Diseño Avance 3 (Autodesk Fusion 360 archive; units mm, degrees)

design "Diseño para imprimir" references "ESP32S3 Super Mini", "TOF", "przelacznik", "Tornillo grueso en forma de rosca sin ranura de arandela hexagonal 30° 5x8 Acero al carbono Negro"
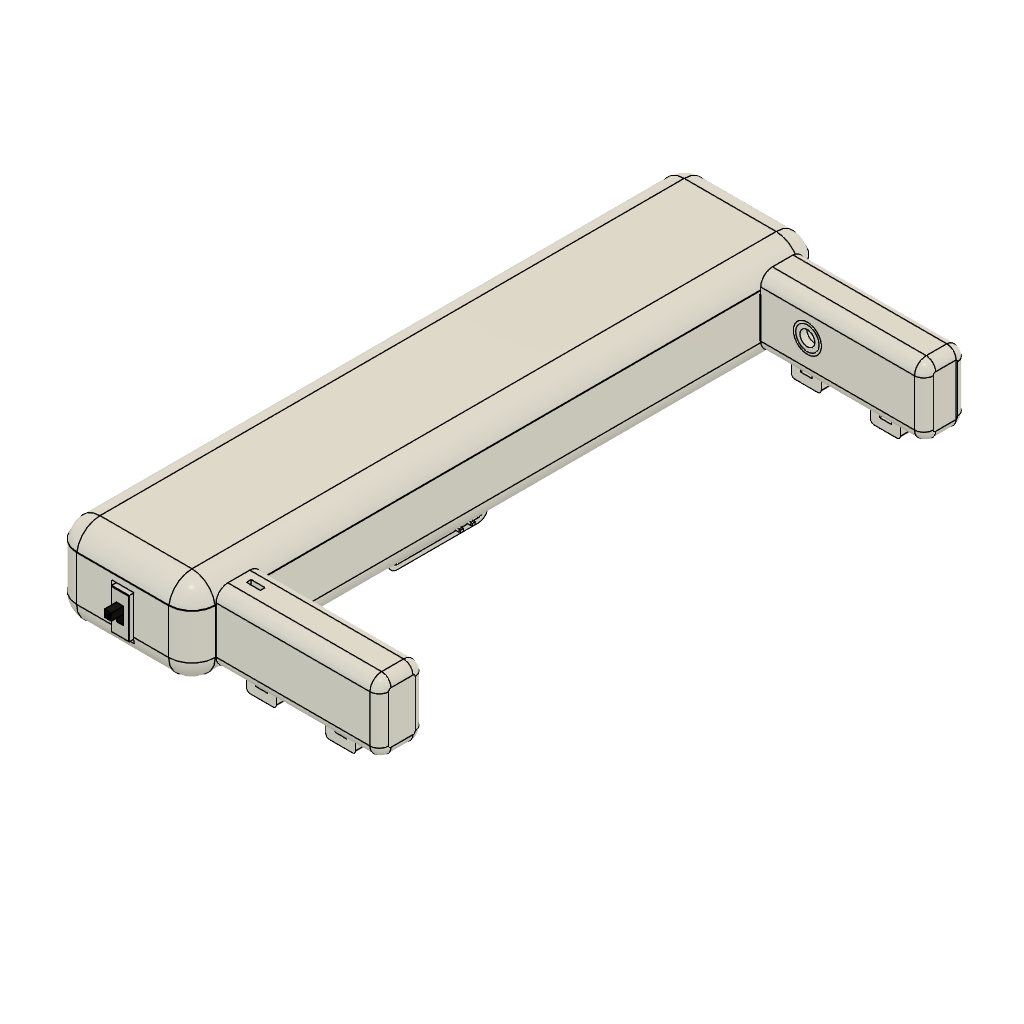
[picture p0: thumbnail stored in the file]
part number: 2026-10-26-12-19-18-322
parameter "d70" = 1.5
parameter "d71" = 2
parameter "d72" = 0.75 (= "0.5 * d70")
parameter "d73" = 0.5
parameter "d74" = 0.1
component_insert "Inserción de componente2"
sketch "Boceto2" plane through (0, 0, 0) normal (0, 1, 0) x axis (1, 0, 0)
  line L1 (11.8049, 39.8827) -> (-7.939, 39.8827)
  line L2 (16.8049, -90.4755) -> (16.8049, 34.8827)
  line L3 (-7.939, -95.4755) -> (11.8049, -95.4755)
  line L4 (-12.939, 34.8827) -> (-12.939, -90.4755)
  arc A1 centre (11.8049, 34.8827) radius 5 clockwise from (11.8049, 39.8827) to (16.8049, 34.8827)
  arc A2 centre (-7.939, 34.8827) radius 5 clockwise from (-12.939, 34.8827) to (-7.939, 39.8827)
  arc A3 centre (11.8049, -90.4755) radius 5 clockwise from (16.8049, -90.4755) to (11.8049, -95.4755)
  arc A4 centre (-7.939, -90.4755) radius 5 clockwise from (-7.939, -95.4755) to (-12.939, -90.4755)
  horizontal L1
  vertical L2
  horizontal L3
  vertical L4
  tangent L1 A1
  tangent L2 A1
  tangent L1 A2
  tangent L4 A2
  equal A1 A2
  tangent L2 A3
  tangent L3 A3
  equal A1 A3
  tangent L3 A4
  tangent L4 A4
  equal A1 A4
  dimension "d1" radius A1 = 5
extrude "Extruir1" new body sketch "Boceto2" along normal blind 20 bodies "Tapa modelo principal"
fillet "Empalme1" radius 5
shell "Vaciado1" innerThickness 1
sketch "Boceto3" plane through (-12.939, 0, 0) normal (-1, 0, 0) x axis (0, 0, 1)
  line L1 (-34.8827, 15) -> (90.4755, 15)
  line L2 (-34.8827, 5) -> (-34.8827, 15)
  line L3 (90.4755, 5) -> (-34.8827, 5)
  line L4 (90.4755, 15) -> (90.4755, 5)
  line L5 (100, 15) -> (-41.9189, 15.051)
split "Dividir1" bodies "Cuerpo modelo principal"
move "Desplazar1"
move "Desplazar2"
move "Desplazar3"
sketch "Boceto4" plane through (0, 0, -40.8827) normal (0, 0, -1) x axis (-1, 0, 0)
  line L1 (-9.8049, 35) -> (9.939, 35)
  line L2 (-9.8049, 25) -> (-9.8049, 35)
  line L3 (9.939, 25) -> (-9.8049, 25)
  line L4 (9.939, 35) -> (9.939, 25)
  line L5 (4.6443, 30.227) -> (-4.4043, 30.227)
  line L6 (5.5543, 27.1633) -> (5.5543, 29.317)
  line L7 (-4.4043, 26.2533) -> (4.6443, 26.2533)
  line L8 (-5.3143, 29.317) -> (-5.3143, 27.1633)
  arc A1 centre (-4.4043, 29.317) radius 0.91 clockwise from (-5.3143, 29.317) to (-4.4043, 30.227)
  arc A2 centre (4.6443, 29.317) radius 0.91 clockwise from (4.6443, 30.227) to (5.5543, 29.317)
  arc A3 centre (-4.4043, 27.1633) radius 0.91 clockwise from (-4.4043, 26.2533) to (-5.3143, 27.1633)
  arc A4 centre (4.6443, 27.1633) radius 0.91 clockwise from (5.5543, 27.1633) to (4.6443, 26.2533)
  horizontal L5
  vertical L6
  horizontal L7
  vertical L8
  tangent L5 A1
  tangent L8 A1
  tangent L5 A2
  tangent L6 A2
  equal A1 A2
  tangent L7 A3
  tangent L8 A3
  equal A1 A3
  tangent L6 A4
  tangent L7 A4
  equal A1 A4
  dimension "d7" radius A1 = 0.91
extrude "Extruir2" cut sketch "Boceto4" profile of L5 L6 L7 L8 A1 A2 A3 A4 distance 5
sketch "Boceto6" plane through (0, 0, 0) normal (0, 1, 0) x axis (1, 0, 0)
  line L1 (-6.6748, -37.6034) -> (5.6853, -37.6034)
  line L2 (-8.6748, -18.2148) -> (-8.6748, -35.6034)
  line L3 (5.6853, -16.2148) -> (-6.6748, -16.2148)
  line L4 (7.6853, -35.6034) -> (7.6853, -18.2148)
  arc A1 centre (5.6853, -35.6034) radius 2 clockwise from (7.6853, -35.6034) to (5.6853, -37.6034)
  arc A2 centre (5.6853, -18.2148) radius 2 clockwise from (5.6853, -16.2148) to (7.6853, -18.2148)
  arc A3 centre (-6.6748, -18.2148) radius 2 clockwise from (-8.6748, -18.2148) to (-6.6748, -16.2148)
  arc A4 centre (-6.6748, -35.6034) radius 2 clockwise from (-6.6748, -37.6034) to (-8.6748, -35.6034)
  horizontal L1
  vertical L2
  horizontal L3
  vertical L4
  tangent L1 A1
  tangent L4 A1
  tangent L3 A2
  tangent L4 A2
  equal A1 A2
  tangent L2 A3
  tangent L3 A3
  equal A1 A3
  tangent L1 A4
  tangent L2 A4
  equal A1 A4
  dimension "d13" radius A1 = 2
extrude "Extruir4" new body sketch "Boceto6" along normal blind 14 bodies "Cuerpo sensor movimiento"
sketch "Boceto5" plane through (0, 0, 0) normal (0, 1, 0) x axis (1, 0, 0)
  line L1 (5.7179, -37.5629) -> (-6.5549, -37.5629)
  line L2 (7.7179, -18.2385) -> (7.7179, -35.5629)
  line L3 (-6.5549, -16.2385) -> (5.7179, -16.2385)
  line L4 (-8.5549, -35.5629) -> (-8.5549, -18.2385)
  arc A1 centre (-6.5549, -18.2385) radius 2 clockwise from (-8.5549, -18.2385) to (-6.5549, -16.2385)
  arc A2 centre (5.7179, -18.2385) radius 2 clockwise from (5.7179, -16.2385) to (7.7179, -18.2385)
  arc A3 centre (-6.5549, -35.5629) radius 2 clockwise from (-6.5549, -37.5629) to (-8.5549, -35.5629)
  arc A4 centre (5.7179, -35.5629) radius 2 clockwise from (7.7179, -35.5629) to (5.7179, -37.5629)
  horizontal L1
  vertical L2
  horizontal L3
  vertical L4
  tangent L3 A1
  tangent L4 A1
  tangent L2 A2
  tangent L3 A2
  equal A1 A2
  tangent L1 A3
  tangent L4 A3
  equal A1 A3
  tangent L1 A4
  tangent L2 A4
  equal A1 A4
  dimension "d12" radius A1 = 2
extrude "Extruir3" cut sketch "Boceto5" profile of L1 L2 L3 L4 along normal blind 30
fillet "Empalme2" radius 2
shell "Vaciado2" innerThickness 1
move "Desplazar7"
component_insert "Inserción de componente5"
sketch "Boceto12" plane through (0, 0, 94.4755) normal (0, 0, 1) x axis (1, 0, 0)
  line L1 (-9.939, 35) -> (9.8049, 35)
  line L2 (-9.939, 25) -> (-9.939, 35)
  line L3 (9.8049, 25) -> (-9.939, 25)
  line L4 (9.8049, 35) -> (9.8049, 25)
  line L5 (2.2736, 33.3192) -> (-2.4332, 33.3192)
  line L6 (2.2736, 23.7329) -> (2.2736, 33.3192)
  line L7 (-2.4332, 23.7329) -> (2.2736, 23.7329)
  line L8 (-2.4332, 33.3192) -> (-2.4332, 23.7329)
  horizontal L5
  vertical L6
  horizontal L7
  vertical L8
position "Posición1"
extrude "Extruir8" cut sketch "Boceto12" profile of L3 L5 L6 L8 along normal blind 2 and against normal blind 2
extrude "Extruir9" cut sketch "Boceto12" profile of L3 L6 L7 L8 along normal blind 0 and against normal blind 2
component_insert "Inserción de componente6"
position "Posición2"
sketch "Boceto14" plane through (0, 0, 0) normal (1, 0, 0) x axis (0, 0, -1)
  line L1 (-26.4911, 15.7408) -> (-22.7799, 15.7408)
  line L2 (-27.4911, 13.343) -> (-27.4911, 14.7408)
  line L3 (-22.7799, 12.343) -> (-26.4911, 12.343)
  line L4 (-21.7799, 14.7408) -> (-21.7799, 13.343)
  arc A1 centre (-22.7799, 14.7408) radius 1 clockwise from (-22.7799, 15.7408) to (-21.7799, 14.7408)
  arc A2 centre (-26.4911, 14.7408) radius 1 clockwise from (-27.4911, 14.7408) to (-26.4911, 15.7408)
  arc A3 centre (-26.4911, 13.343) radius 1 clockwise from (-26.4911, 12.343) to (-27.4911, 13.343)
  arc A4 centre (-22.7799, 13.343) radius 1 clockwise from (-21.7799, 13.343) to (-22.7799, 12.343)
  horizontal L1
  vertical L2
  horizontal L3
  vertical L4
  tangent L1 A1
  tangent L4 A1
  tangent L1 A2
  tangent L2 A2
  equal A1 A2
  tangent L2 A3
  tangent L3 A3
  equal A1 A3
  tangent L3 A4
  tangent L4 A4
  equal A1 A4
  dimension "d41" radius A1 = 1
extrude "Extruir10" cut sketch "Boceto14" along normal blind 0 and against normal blind 25
sketch "Boceto15" plane through (0, 0, 0) normal (1, 0, 0) x axis (0, 0, -1)
  line L1 (-27.8639, 17.9865) -> (-21.8979, 17.9865)
  line L2 (-29.8639, 12.5238) -> (-29.8639, 15.9865)
  line L3 (-21.8979, 10.5238) -> (-27.8639, 10.5238)
  line L4 (-19.8979, 15.9865) -> (-19.8979, 12.5238)
  arc A1 centre (-21.8979, 15.9865) radius 2 clockwise from (-21.8979, 17.9865) to (-19.8979, 15.9865)
  arc A2 centre (-27.8639, 15.9865) radius 2 clockwise from (-29.8639, 15.9865) to (-27.8639, 17.9865)
  arc A3 centre (-27.8639, 12.5238) radius 2 clockwise from (-27.8639, 10.5238) to (-29.8639, 12.5238)
  arc A4 centre (-21.8979, 12.5238) radius 2 clockwise from (-19.8979, 12.5238) to (-21.8979, 10.5238)
  horizontal L1
  vertical L2
  horizontal L3
  vertical L4
  tangent L1 A1
  tangent L4 A1
  tangent L1 A2
  tangent L2 A2
  equal A1 A2
  tangent L2 A3
  tangent L3 A3
  equal A1 A3
  tangent L3 A4
  tangent L4 A4
  equal A1 A4
  dimension "d46" radius A1 = 2
extrude "Extruir11" new body sketch "Boceto15" against normal blind 9 and against normal blind 14 bodies "Tapa protector sensor"
shell "Vaciado4" innerThickness 1
sketch "Boceto16" plane through (-8.6748, 0, 0) normal (-1, 0, 0) x axis (0, 0, 1)
  line L1 (21.7799, 14.7408) -> (21.7799, 13.343)
  line L2 (26.4911, 15.7408) -> (22.7799, 15.7408)
  line L3 (27.4911, 13.343) -> (27.4911, 14.7408)
  line L4 (22.7799, 12.343) -> (26.4911, 12.343)
  line L5 (35.6034, 9) -> (18.2148, 9)
  line L6 (35.6034, 21) -> (35.6034, 9)
  line L7 (18.2148, 21) -> (35.6034, 21)
  line L8 (18.2148, 9) -> (18.2148, 21)
  line L9 (26.4581, 16) -> (22.7339, 16)
  line L10 (27.4581, 13.3266) -> (27.4581, 15)
  line L11 (22.7339, 12.3266) -> (26.4581, 12.3266)
  line L12 (21.7339, 15) -> (21.7339, 13.3266)
  arc A1 centre (22.7799, 14.7408) radius 1 clockwise from (21.7799, 14.7408) to (22.7799, 15.7408)
  arc A2 centre (26.4911, 14.7408) radius 1 clockwise from (26.4911, 15.7408) to (27.4911, 14.7408)
  arc A3 centre (26.4911, 13.343) radius 1 clockwise from (27.4911, 13.343) to (26.4911, 12.343)
  arc A4 centre (22.7799, 13.343) radius 1 clockwise from (22.7799, 12.343) to (21.7799, 13.343)
  arc A5 centre (22.7339, 15) radius 1 clockwise from (21.7339, 15) to (22.7339, 16)
  arc A6 centre (26.4581, 15) radius 1 clockwise from (26.4581, 16) to (27.4581, 15)
  arc A7 centre (26.4581, 13.3266) radius 1 clockwise from (27.4581, 13.3266) to (26.4581, 12.3266)
  arc A8 centre (22.7339, 13.3266) radius 1 clockwise from (22.7339, 12.3266) to (21.7339, 13.3266)
  horizontal L9
  vertical L10
  horizontal L11
  vertical L12
  tangent L9 A5
  tangent L12 A5
  tangent L9 A6
  tangent L10 A6
  equal A5 A6
  tangent L10 A7
  tangent L11 A7
  equal A5 A7
  tangent L11 A8
  tangent L12 A8
  equal A5 A8
  dimension "d52" radius A5 = 1
extrude "Extruir12" cut sketch "Boceto16" profile of L1 A1 L2 A2 A3 L4 A4 L10 A7 along normal blind 2
sketch "Boceto17" plane through (13.8049, 0, 0) normal (-1, 0, 0) x axis (0, 0, 1)
  line L1 (89.4755, 35) -> (89.4755, 25)
  line L2 (-35.8827, 35) -> (89.4755, 35)
  line L3 (-35.8827, 25) -> (-35.8827, 35)
  line L4 (89.4755, 25) -> (-35.8827, 25)
  line L5 (-21, 33) -> (-27, 33)
  line L6 (-20, 27.8856) -> (-20, 32)
  line L7 (-27, 26.8856) -> (-21, 26.8856)
  line L8 (-28, 32) -> (-28, 27.8856)
  arc A1 centre (-27, 32) radius 1 clockwise from (-28, 32) to (-27, 33)
  arc A2 centre (-27, 32) radius 1 clockwise from (-28, 32) to (-27, 33)
  arc A3 centre (-21, 27.8856) radius 1 clockwise from (-20, 27.8856) to (-21, 26.8856)
  arc A4 centre (-21, 32) radius 1 clockwise from (-21, 33) to (-20, 32)
  arc A5 centre (-27, 27.8856) radius 1 clockwise from (-27, 26.8856) to (-28, 27.8856)
  point P6 (-27, 33)
  point P7 (-28, 32)
  horizontal L5
  vertical L6
  horizontal L7
  vertical L8
  tangent L5 A1
  tangent L8 A1
  coincident L5 P6
  coincident L8 P7
  tangent L5 A2
  tangent L8 A2
  equal A1 A2
  tangent L6 A3
  tangent L7 A3
  equal A1 A3
  tangent L5 A4
  tangent L6 A4
  equal A1 A4
  tangent L7 A5
  tangent L8 A5
  equal A1 A5
  dimension "d55" radius A1 = 1
sketch "Boceto18" plane through (0, 0, 0) normal (1, 0, 0) x axis (0, 0, -1)
  circle C1 centre (-45, -20) radius 5
extrude "Extruir14" new body sketch "Boceto18" along normal blind 3 bodies "motor vibrador"
move "Desplazar10"
sketch "Boceto20" plane through (0, 0, 0) normal (1, 0, 0) x axis (0, 0, -1)
  line L1 (26.6011, 37.0201) -> (21.889, 37.0201)
  line L2 (29.1011, 24.4442) -> (29.1011, 34.5201)
  line L3 (21.889, 21.9442) -> (26.6011, 21.9442)
  line L4 (19.389, 34.5201) -> (19.389, 24.4442)
  arc A1 centre (21.889, 34.5201) radius 2.5 clockwise from (19.389, 34.5201) to (21.889, 37.0201)
  arc A2 centre (26.6011, 34.5201) radius 2.5 clockwise from (26.6011, 37.0201) to (29.1011, 34.5201)
  arc A3 centre (26.6011, 24.4442) radius 2.5 clockwise from (29.1011, 24.4442) to (26.6011, 21.9442)
  arc A4 centre (21.889, 24.4442) radius 2.5 clockwise from (21.889, 21.9442) to (19.389, 24.4442)
  horizontal L1
  vertical L2
  horizontal L3
  vertical L4
  tangent L1 A1
  tangent L4 A1
  tangent L1 A2
  tangent L2 A2
  equal A1 A2
  tangent L2 A3
  tangent L3 A3
  equal A1 A3
  tangent L3 A4
  tangent L4 A4
  equal A1 A4
  dimension "d62" radius A1 = 2.5
extrude "Extruir15" new body sketch "Boceto20" along normal blind 80 and along normal blind 45
fillet "Empalme4" radius 2
copy_paste_bodies "CopiarPegarCuerpos1"
move "Desplazar11"
shell "Vaciado5" innerThickness 1.5
move "Desplazar12"
move "Desplazar13"
move "Desplazar14"
sketch "Boceto21" plane through (70, 0, 0) normal (1, 0, 0) x axis (0, 0, -1)
  line L1 (26.6011, 21.9442) -> (21.889, 21.9442)
  line L2 (27.1011, 32.5201) -> (27.1011, 22.4442)
  line L3 (21.889, 33.0201) -> (26.6011, 33.0201)
  line L4 (21.389, 22.4442) -> (21.389, 32.5201)
  line L5 (26.5532, 17.0167) -> (26.5532, 37)
  arc A1 centre (26.6011, 22.4442) radius 0.5 clockwise from (27.1011, 22.4442) to (26.6011, 21.9442)
  arc A2 centre (26.6011, 32.5201) radius 0.5 clockwise from (26.6011, 33.0201) to (27.1011, 32.5201)
  arc A3 centre (21.889, 32.5201) radius 0.5 clockwise from (21.389, 32.5201) to (21.889, 33.0201)
  arc A4 centre (21.889, 22.4442) radius 0.5 clockwise from (21.889, 21.9442) to (21.389, 22.4442)
  vertical L5
split "Dividir2" bodies "Cabidad motor"
move "Desplazar15"
move "Desplazar16"
move "Desplazar17"
move "Desplazar18"
move "Desplazar19"
move "Desplazar20"
move "Desplazar21"
move "Desplazar22"
move "Desplazar23"
move "Desplazar25"
step "Labio1" Height (A) 0.5 (= "d70 / 3") Width (B) 0.5 (= "d70 / 3") Shoulder Width (C) 0 Inside Angle (a1) 2 (= "d71") Outside Angle (a2) 2 (= "d71") Reveal Height (D) 0.5 (= "d73") Clearance (E) 0.1 (= "d74")
step "Labio2" Height (A) 0.5 (= "d70 / 3") Width (B) 0.5 (= "d70 / 3") Shoulder Width (C) 0 Inside Angle (a1) 2 (= "d71") Outside Angle (a2) 2 (= "d71") Reveal Height (D) 0.5 (= "d73") Clearance (E) 0.1 (= "d74")
move "Desplazar26"
sketch "Boceto26" plane through (0, 0, 0) normal (0, 1, 0) x axis (1, 0, 0)
  line L1 (-85, -40) -> (-65, -40)
  line L2 (-85, -10) -> (-85, -40)
  line L3 (-65, -10) -> (-85, -10)
  line L4 (-65, -40) -> (-65, -10)
  horizontal L1
  vertical L2
  horizontal L3
  vertical L4
extrude "Extruir17" new body sketch "Boceto26" along normal blind 9
move "Desplazar27"
move "Desplazar28"
sketch "Boceto27" plane through (0, 21, 0) normal (0, 1, 0) x axis (-1, 0, 0)
  line L1 (6.5549, 37.5629) -> (-5.7179, 37.5629)
  line L2 (8.5549, 18.2385) -> (8.5549, 35.5629)
  line L3 (-5.7179, 16.2385) -> (6.5549, 16.2385)
  line L4 (-7.7179, 35.5629) -> (-7.7179, 18.2385)
  line L5 (9.939, -35.8827) -> (-9.8049, -35.8827)
  line L6 (9.939, 89.4755) -> (9.939, -35.8827)
  line L7 (-9.8049, 89.4755) -> (9.939, 89.4755)
  line L8 (-9.8049, -35.8827) -> (-9.8049, 89.4755)
  arc A1 centre (6.5549, 35.5629) radius 2 clockwise from (6.5549, 37.5629) to (8.5549, 35.5629)
  arc A2 centre (6.5549, 18.2385) radius 2 clockwise from (8.5549, 18.2385) to (6.5549, 16.2385)
  arc A3 centre (-5.7179, 18.2385) radius 2 clockwise from (-5.7179, 16.2385) to (-7.7179, 18.2385)
  arc A4 centre (-5.7179, 35.5629) radius 2 clockwise from (-7.7179, 35.5629) to (-5.7179, 37.5629)
  circle C1 centre (0, 10) radius 3
  circle C2 centre (0, 45) radius 3
move "Desplazar29"
step "Saliente de Fijación3" Thickness(T1) 1.5 (= "d70") named "d179" Draft Angle(DA1) 2 (= "d71") named "d180" Nominal Radius(NR1) 0.75 (= "d72") Thread Diameter(TD) 5 named "d182" Head Diameter(HD) 10 named "d183" Head Angle(HA) 0 named "d184" Offset Position(O) 0 Offset Clearance(O1) 0 Boss Diameter(D1) 12 (= "d200 + d179") Boss Draft Angle(alpha41) 2 (= "d180") Base Fillet Radius(R1) 0.375 (= "d179 * 0.25") Outer Boss Fillet Radius(R51) 0 Step Diameter(C1) 3 Step Depth(F1) 1 Step Draft Angle(alpha31) 0 Outer Step Fillet Radius(R61) 0 Inner Step Fillet Radius(R71) 0 Inner Hole Diameter(B1) 5.5 (= "d182 + 0.5 mm") Hole Draft Angle(alpha21) 2 (= "d180") Outer Counterbore Fillet Radius(R11) 0 Inner Counterbore Fillet Radius(R41) 0 Counterbore Diameter(A1) 10.5 (= "d183 + 0.5 mm") named "d200" Inner Hole Depth(E1) 2.5 (= "d179 + 1 mm") Counterbore Draft Angle(alpha11) 2 (= "d180") Lower Hole Fillet Radius(R31) 0 Upper Hole Fillet Radius(R21) 0 Countersink Angle(alpha1) 0 (= "d184") Inner Hole Depth(G1) 0 Rib Length(K1) 0 Rib Offset(L1) 0 Rib Thickness(RT1) 0 Rib Draft Angle(RD1) 0 Rib Fillet Radius(RR1) 0 Rib Outer Draft(beta11) 0 Rib Chamfer Angle(beta21) 0 Rib Outer Fillet Radius(RTR1) 0 Rib Base Fillet Radius(RBR1) 0 Rib Rotation Angle(RRO1) 0 Rib Total Angle(RAS1) 360
step "Saliente de Fijación5" Thickness(T1) 1.5 (= "d70") named "d259" Draft Angle(DA1) 2 (= "d71") named "d260" Nominal Radius(NR1) 0.75 (= "d72") Thread Diameter(TD) 5 named "d262" Head Diameter(HD) 10 named "d263" Head Angle(HA) 0 named "d264" Offset Position(O) 0 Offset Clearance(O1) 0 Boss Diameter(D1) 12 (= "d280 + d259") Boss Draft Angle(alpha41) 2 (= "d260") Base Fillet Radius(R1) 0.375 (= "d259 * 0.25") Outer Boss Fillet Radius(R51) 0 Step Diameter(C1) 3 Step Depth(F1) 1 Step Draft Angle(alpha31) 0 Outer Step Fillet Radius(R61) 0 Inner Step Fillet Radius(R71) 0 Inner Hole Diameter(B1) 5.5 (= "d262 + 0.5 mm") Hole Draft Angle(alpha21) 2 (= "d260") Outer Counterbore Fillet Radius(R11) 0 Inner Counterbore Fillet Radius(R41) 0 Counterbore Diameter(A1) 10.5 (= "d263 + 0.5 mm") named "d280" Inner Hole Depth(E1) 2.5 (= "d259 + 1 mm") Counterbore Draft Angle(alpha11) 2 (= "d260") Lower Hole Fillet Radius(R31) 0 Upper Hole Fillet Radius(R21) 0 Countersink Angle(alpha1) 0 (= "d264") Inner Hole Depth(G1) 0 Rib Length(K1) 0 Rib Offset(L1) 0 Rib Thickness(RT1) 0 Rib Draft Angle(RD1) 0 Rib Fillet Radius(RR1) 0 Rib Outer Draft(beta11) 0 Rib Chamfer Angle(beta21) 0 Rib Outer Fillet Radius(RTR1) 0 Rib Base Fillet Radius(RBR1) 0 Rib Rotation Angle(RRO1) 0 Rib Total Angle(RAS1) 360
move "Desplazar30"
step "Labio3" Height (A) 0.5 (= "d70 / 3") Width (B) 0.5 (= "d70 / 3") Shoulder Width (C) 0 Inside Angle (a1) 2 (= "d71") Outside Angle (a2) 2 (= "d71") Reveal Height (D) 0.5 (= "d73") Clearance (E) 0.1 (= "d74")
step "Labio4" Height (A) 0.5 (= "d70 / 3") Width (B) 0.5 (= "d70 / 3") Shoulder Width (C) 0 Inside Angle (a1) 2 (= "d71") Outside Angle (a2) 2 (= "d71") Reveal Height (D) 0.5 (= "d73") Clearance (E) 0.1 (= "d74")
move "Desplazar31"
move "Desplazar32"
move "Desplazar33"
move "Desplazar34"
move "Desplazar35"
move "Desplazar36"
move "Desplazar37"
sketch "Boceto29" plane through (33.6144, 0, 0) normal (-1, 0, 0) x axis (0, 0, 1)
  line L1 (82.3783, 37.8511) -> (87.0904, 37.8511)
  line L2 (79.8783, 25.2751) -> (79.8783, 35.3511)
  line L3 (87.0904, 22.7751) -> (82.3783, 22.7751)
  line L4 (89.5904, 35.3511) -> (89.5904, 25.2751)
  line L5 (86, 33.9849) -> (83, 33.9849)
  line L6 (86, 26) -> (86, 33.9849)
  line L7 (83, 26) -> (86, 26)
  line L8 (83, 33.9849) -> (83, 26)
  arc A1 centre (87.0904, 35.3511) radius 2.5 clockwise from (87.0904, 37.8511) to (89.5904, 35.3511)
  arc A2 centre (82.3783, 35.3511) radius 2.5 clockwise from (79.8783, 35.3511) to (82.3783, 37.8511)
  arc A3 centre (82.3783, 25.2751) radius 2.5 clockwise from (82.3783, 22.7751) to (79.8783, 25.2751)
  arc A4 centre (87.0904, 25.2751) radius 2.5 clockwise from (89.5904, 25.2751) to (87.0904, 22.7751)
  horizontal L5
  vertical L6
  horizontal L7
  vertical L8
extrude "Extruir18" cut sketch "Boceto29" profile of L5 L6 L7 L8 along normal blind 0 and against normal blind 6
sketch "Boceto30" plane through (14.8049, 0, 0) normal (1, 0, 0) x axis (0, 0, -1)
  line L1 (-89.4755, 34.7534) -> (35.8827, 34.7985)
  line L2 (-89.4755, 25) -> (-89.4755, 34.7534)
  line L3 (35.8827, 25) -> (-89.4755, 25)
  line L4 (35.8827, 34.7985) -> (35.8827, 25)
  line L5 (-83, 33.9927) -> (-86, 33.9927)
  line L6 (-83, 26) -> (-83, 33.9927)
  line L7 (-86, 26) -> (-83, 26)
  line L8 (-86, 33.9927) -> (-86, 26)
  horizontal L5
  vertical L6
  horizontal L7
  vertical L8
extrude "Extruir19" add sketch "Boceto30" profile of L5 L6 L7 L8 along normal blind 6
sketch "Boceto31" plane through (0, 0, -47.6011) normal (0, 0, -1) x axis (-1, 0, 0)
  line L1 (-68, 22.3942) -> (-68, 32.4701)
  line L2 (-35, 22.3942) -> (-68, 22.3942)
  line L3 (-35, 32.4701) -> (-35, 22.3942)
  line L4 (-68, 32.4701) -> (-35, 32.4701)
move "Desplazar38"
move "Desplazar39"
move "Desplazar40"
move "Desplazar41"
move "Desplazar42"
sketch "Boceto33" plane through (0, 0, -20.889) normal (0, 0, -1) x axis (-1, 0, 0)
  line L1 (-68, 22.4442) -> (-68, 32.5201)
  line L2 (-35, 22.4442) -> (-68, 22.4442)
  line L3 (-35, 32.5201) -> (-35, 22.4442)
  line L4 (-68, 32.5201) -> (-35, 32.5201)
  circle C1 centre (-45, 28) radius 3
move "Desplazar43"
move "Desplazar44"
move "Desplazar45"
move "Desplazar46"
move "Desplazar47"
move "Desplazar48"
move "Desplazar49"
sketch "Boceto34" plane through (14.8049, 0, 0) normal (1, 0, 0) x axis (0, 0, -1)
  line L1 (-86, 33.9927) -> (-86, 26)
  line L2 (-83, 33.9927) -> (-86, 33.9927)
  line L3 (-83, 26) -> (-83, 33.9927)
  line L4 (-86, 26) -> (-83, 26)
  line L5 (-89.4755, 34.7534) -> (35.8827, 34.7985)
  line L6 (-89.4755, 25) -> (-89.4755, 34.7534)
  line L7 (35.8827, 25) -> (-89.4755, 25)
  line L8 (35.8827, 34.7985) -> (35.8827, 25)
  line L9 (34.1126, 34.1796) -> (29.8976, 34.1796)
  line L10 (34.1126, 25.7924) -> (34.1126, 34.1796)
  line L11 (29.8976, 25.7924) -> (34.1126, 25.7924)
  line L12 (29.8976, 34.1796) -> (29.8976, 25.7924)
  horizontal L9
  vertical L10
  horizontal L11
  vertical L12
extrude "Extruir24" cut sketch "Boceto34" profile of L9 L10 L11 L12 along normal blind 0 and against normal blind 2
move "Desplazar50"
move "Desplazar51"
move "Desplazar53"
sketch "Boceto36" plane through (22, 0, 0) normal (-1, 0, 0) x axis (0, 0, 1)
  line L1 (-34.3032, 22.9442) -> (-34.3032, 23.9355)
  line L2 (-29.889, 22.9442) -> (-34.3032, 22.9442)
  line L3 (-34.3032, 38.0201) -> (-29.889, 38.0201)
  line L4 (-34.3032, 37.0289) -> (-34.3032, 38.0201)
  line L5 (-35.0532, 37.0027) -> (-34.3032, 37.0289)
  line L6 (-35.0532, 36.5376) -> (-35.0532, 37.0027)
  line L7 (-34.5532, 36.5201) -> (-35.0532, 36.5376)
  line L8 (-29.889, 36.5201) -> (-34.5532, 36.5201)
  line L9 (-28.889, 25.4442) -> (-28.889, 35.5201)
  line L10 (-34.5532, 24.4442) -> (-29.889, 24.4442)
  line L11 (-35.0532, 24.4267) -> (-34.5532, 24.4442)
  line L12 (-35.0532, 23.9616) -> (-35.0532, 24.4267)
  line L13 (-34.3032, 23.9355) -> (-35.0532, 23.9616)
  line L14 (-35.1468, 34.0189) -> (-36.5632, 34.0189)
  line L15 (-35.1468, 25.4548) -> (-35.1468, 34.0189)
  line L16 (-36.5632, 25.4548) -> (-35.1468, 25.4548)
  line L17 (-36.5632, 34.0189) -> (-36.5632, 25.4548)
  line L18 (-27.3997, 34.0189) -> (-28.889, 34.0189)
  line L19 (-27.3997, 25.4616) -> (-27.3997, 34.0189)
  line L20 (-28.889, 25.4616) -> (-27.3997, 25.4616)
  line L21 (-28.889, 34.0189) -> (-28.889, 25.4616)
  arc A1 centre (-29.889, 25.4442) radius 2.5 clockwise from (-27.389, 25.4442) to (-29.889, 22.9442)
  arc A2 centre (-29.889, 35.5201) radius 2.5 clockwise from (-29.889, 38.0201) to (-27.389, 35.5201)
  arc A3 centre (-29.889, 35.5201) radius 1 clockwise from (-29.889, 36.5201) to (-28.889, 35.5201)
  arc A4 centre (-29.889, 25.4442) radius 1 clockwise from (-28.889, 25.4442) to (-29.889, 24.4442)
  point P26 (-28.889, 34.0189)
  horizontal L14
  vertical L15
  horizontal L16
  vertical L17
  horizontal L18
  vertical L19
  horizontal L20
  vertical L21
  coincident L9 P26
extrude "Extruir25" add sketch "Boceto36" profile of A1 L9 along normal blind 3
extrude "Extruir26" add sketch "Boceto36" profile of L14 L15 L16 L17 along normal blind 3
extrude "Extruir27" cut sketch "Boceto36" profile of L14 L15 L16 L17 along normal blind 15
extrude "Extruir28" cut sketch "Boceto36" profile of L9 L18 L19 L20 L21 along normal blind 9
move "Desplazar58"
move "Desplazar59"
combine "Combinar1" bodies "Modelo principal", "Cuerpo sensor movimiento"
combine "Combinar2" bodies "Cuerpo modelo principal"
move "Desplazar60"
combine "Combinar3" bodies "Tapa protector sensor"
move "Desplazar61"
move "Desplazar62"
sketch "Boceto40" plane through (0, 0, 0) normal (0, 0, 1) x axis (1, 0, 0)
  line L1 (63.1533, 0) -> (45.5, 0)
  line L2 (63.6533, -3.7135) -> (63.6533, -0.5)
  line L3 (45.5, -4.2135) -> (63.1533, -4.2135)
  line L4 (45, -0.5) -> (45, -3.7135)
  arc A1 centre (45.5, -0.5) radius 0.5 clockwise from (45, -0.5) to (45.5, 0)
  arc A2 centre (45.5, -3.7135) radius 0.5 clockwise from (45.5, -4.2135) to (45, -3.7135)
  arc A3 centre (63.1533, -0.5) radius 0.5 clockwise from (63.1533, 0) to (63.6533, -0.5)
  arc A4 centre (63.1533, -3.7135) radius 0.5 clockwise from (63.6533, -3.7135) to (63.1533, -4.2135)
  horizontal L1
  vertical L2
  horizontal L3
  vertical L4
  tangent L1 A1
  tangent L4 A1
  tangent L3 A2
  tangent L4 A2
  equal A1 A2
  tangent L1 A3
  tangent L2 A3
  equal A1 A3
  tangent L2 A4
  tangent L3 A4
  equal A1 A4
  dimension "d475" radius A1 = 0.5
extrude "Extruir29" new body sketch "Boceto40" along normal blind 29.17 bodies "Sostenedor de ESP32"
move "Desplazar63"
sketch "Boceto41" plane through (0, 25, 0) normal (0, 1, 0) x axis (-1, 0, 0)
  line L1 (8.5, -40) -> (-9.1533, -40)
  line L2 (8.5, -10.83) -> (8.5, -40)
  line L3 (-9.1533, -10.83) -> (8.5, -10.83)
  line L4 (-9.1533, -40) -> (-9.1533, -10.83)
  line L5 (8.4852, -15.1354) -> (-9.1533, -15.1354)
  line L6 (8.4852, -11) -> (8.4852, -15.1354)
  line L7 (-9.1533, -11) -> (8.4852, -11)
  line L8 (-9.1533, -15.1354) -> (-9.1533, -11)
  point P6 (-9.1533, -15.1354)
  horizontal L5
  vertical L6
  horizontal L7
  vertical L8
  coincident L4 P6
extrude "Extruir30" add sketch "Boceto41" profile of L4 L5 L6 L7 L8 along normal blind 5
move "Desplazar64"
move "Desplazar65"
move "Desplazar66"
move "Desplazar67"
sketch "Boceto42" plane through (15, 0, 0) normal (-1, 0, 0) x axis (0, 0, 1)
  line L1 (-36.5632, 34.0189) -> (-36.5632, 25.4548)
  line L2 (-35.1468, 34.0189) -> (-36.5632, 34.0189)
  line L3 (-35.1468, 25.4548) -> (-35.1468, 34.0189)
  line L4 (-36.5632, 25.4548) -> (-35.1468, 25.4548)
  line L5 (-34.3032, 23.8629) -> (-34.3032, 22.9624)
  line L6 (-34.6532, 23.8751) -> (-34.3032, 23.8629)
  line L7 (-34.6532, 24.5333) -> (-34.6532, 23.8751)
  line L8 (-34.503, 24.5385) -> (-34.6532, 24.5333)
  line L9 (-35.1011, 35.5301) -> (-35.1011, 25.4542)
  line L10 (-34.6532, 36.451) -> (-34.503, 36.4458)
  line L11 (-34.6532, 37.1093) -> (-34.6532, 36.451)
  line L12 (-34.3032, 37.1215) -> (-34.6532, 37.1093)
  line L13 (-34.3032, 38.022) -> (-34.3032, 37.1215)
  line L14 (-36.6011, 25.4542) -> (-36.6011, 35.5301)
  line L15 (-26.0173, 36) -> (-38.0157, 36)
  line L16 (-26.0173, 34.0259) -> (-26.0173, 36)
  line L17 (-38.0157, 34.0259) -> (-26.0173, 34.0259)
  line L18 (-38.0157, 36) -> (-38.0157, 34.0259)
  line L19 (-26.0173, 34.0259) -> (-27.3118, 34.0259)
  line L20 (-26.0173, 24.9579) -> (-26.0173, 34.0259)
  line L21 (-27.3118, 24.9579) -> (-26.0173, 24.9579)
  line L22 (-27.3118, 34.0259) -> (-27.3118, 24.9579)
  line L23 (-36.5513, 34.0259) -> (-38.0157, 34.0259)
  line L24 (-36.5513, 24.9579) -> (-36.5513, 34.0259)
  line L25 (-38.0157, 24.9579) -> (-36.5513, 24.9579)
  line L26 (-38.0157, 34.0259) -> (-38.0157, 24.9579)
  line L27 (-26, 25.1843) -> (-38.0157, 25.1843)
  line L28 (-26, 21.676) -> (-26, 25.1843)
  line L29 (-38.0157, 21.676) -> (-26, 21.676)
  line L30 (-38.0157, 25.1843) -> (-38.0157, 21.676)
  arc A1 centre (-34.1011, 25.4542) radius 1 clockwise from (-34.503, 24.5385) to (-35.1011, 25.4542)
  arc A2 centre (-34.1011, 35.5301) radius 1 clockwise from (-35.1011, 35.5301) to (-34.503, 36.4458)
  arc A3 centre (-34.1011, 35.5301) radius 2.5 clockwise from (-36.6011, 35.5301) to (-34.3032, 38.022)
  arc A4 centre (-34.1011, 25.4542) radius 2.5 clockwise from (-34.3032, 22.9624) to (-36.6011, 25.4542)
  point P26 (-27.3118, 34.0259)
  point P31 (-36.5513, 24.9579)
  point P33 (-38.0157, 25.1843)
  horizontal L15
  vertical L16
  horizontal L17
  vertical L18
  horizontal L19
  vertical L20
  horizontal L21
  vertical L22
  coincident L17 P26
  horizontal L23
  vertical L24
  horizontal L25
  vertical L26
  coincident A4 P31
  horizontal L27
  vertical L28
  horizontal L29
  vertical L30
  coincident L26 P33
extrude "Extruir31" new body sketch "Boceto42" profile of L5 L6 L7 L8 A1 L9 A2 A3 L14 A4 L15 L16 L17 L18 L19 L20 L21 L22 L23 L24 L25 L26 L27 L28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 along normal blind 2 bodies "Sostenedor de brazo"
move "Desplazar68"
move "Desplazar69"
sketch "Boceto43" plane through (0, 0, -14.1354) normal (0, 0, -1) x axis (-1, 0, 0)
  line L1 (8.4852, 25) -> (-9.1533, 25)
  line L2 (8.4852, 30) -> (8.4852, 25)
  line L3 (-9.1533, 30) -> (8.4852, 30)
  line L4 (-9.1533, 25) -> (-9.1533, 30)
  line L5 (6.2963, 30) -> (-6.8352, 30)
  line L6 (6.2963, 28.8261) -> (6.2963, 30)
  line L7 (-6.8352, 28.8261) -> (6.2963, 28.8261)
  line L8 (-6.8352, 30) -> (-6.8352, 28.8261)
  point P6 (-6.8352, 30)
  horizontal L5
  vertical L6
  horizontal L7
  vertical L8
  coincident L3 P6
extrude "Extruir32" add sketch "Boceto43" profile of L3 L4 along normal blind 10
hole "Agujero" HoleDepth 4.1 HoleDiameter 5 TipAngle 180
sketch "Boceto45" plane through (0, 37.8511, 0) normal (0, 1, 0) x axis (-1, 0, 0)
  line L1 (-48.1144, 82.3783) -> (-48.1144, 87.0904)
  line L2 (-15.1144, 82.3783) -> (-48.1144, 82.3783)
  line L3 (-15.1144, 87.0904) -> (-15.1144, 82.3783)
  line L4 (-48.1144, 87.0904) -> (-15.1144, 87.0904)
sketch "Boceto46" plane through (0, 0, 0) normal (1, 0, 0) x axis (0, 0, -1)
move "Desplazar75"
move "Desplazar76"
move "Desplazar77"
sketch "Boceto49" plane through (0, 0, -28.889) normal (0, 0, -1) x axis (-1, 0, 0)
  line L1 (-48, 25.4442) -> (-48, 35.5201)
  line L2 (-15, 25.4442) -> (-48, 25.4442)
  line L3 (-15, 25.4616) -> (-15, 25.4442)
  line L4 (-12, 25.4616) -> (-15, 25.4616)
  line L5 (-12, 34.0189) -> (-12, 25.4616)
  line L6 (-15, 34.0189) -> (-12, 34.0189)
  line L7 (-15, 35.5201) -> (-15, 34.0189)
  line L8 (-48, 35.5201) -> (-15, 35.5201)
  circle C1 centre (-25, 30) radius 3
sketch "Boceto50" plane through (0, 0, -27.389) normal (0, 0, 1) x axis (1, 0, 0)
  line L1 (48, 35.5201) -> (48, 25.4442)
  line L2 (15, 35.5201) -> (48, 35.5201)
  line L3 (15, 25.4442) -> (15, 35.5201)
  line L4 (48, 25.4442) -> (15, 25.4442)
  circle C1 centre (25, 31) radius 3
  circle C2 centre (25, 31) radius 2.5
  concentric C1 C2
extrude "Extruir36" new body sketch "Boceto50" profile of C1 C2 along normal blind 0 and against normal blind 9.2
extrude "Extruir37" cut sketch "Boceto50" profile of C2 along normal blind 0 and against normal blind 4
combine "Combinar4"
move "Desplazar80"
sketch "Boceto51" plane through (6.6853, 0, 0) normal (-1, 0, 0) x axis (0, 0, 1)
  line L1 (18.2148, 9) -> (18.2148, 21)
  line L2 (35.6034, 9) -> (18.2148, 9)
  line L3 (35.6034, 21) -> (35.6034, 9)
  line L4 (18.2148, 21) -> (35.6034, 21)
  line L5 (35, 21) -> (18.7054, 21)
  line L6 (35, 19) -> (35, 21)
  line L7 (18.7054, 19) -> (35, 19)
  line L8 (18.7054, 21) -> (18.7054, 19)
  point P6 (18.7054, 21)
  horizontal L5
  vertical L6
  horizontal L7
  vertical L8
  coincident L4 P6
sketch "Boceto52" plane through (0, 0, 36.6034) normal (0, 0, -1) x axis (-1, 0, 0)
  line L1 (-5.6853, 9) -> (-5.6853, 21)
  line L2 (6.6748, 9) -> (-5.6853, 9)
  line L3 (6.6748, 21) -> (6.6748, 9)
  line L4 (-5.6853, 21) -> (6.6748, 21)
  line L5 (2.2786, 16.0819) -> (0.47, 16.0819)
  line L6 (2.2786, 11.2667) -> (2.2786, 16.0819)
  line L7 (0.47, 11.2667) -> (2.2786, 11.2667)
  line L8 (0.47, 16.0819) -> (0.47, 11.2667)
  horizontal L5
  vertical L6
  horizontal L7
  vertical L8
extrude "Extruir39" new body sketch "Boceto51" profile of L4 L5 L6 L7 L8 along normal blind 10
extrude "Extruir40" add sketch "Boceto52" profile of L5 L6 L7 L8 along normal blind 20
sketch "Boceto54" plane through (0, 21, 0) normal (0, 1, 0) x axis (-1, 0, 0)
  line L1 (-7.6853, 18.2148) -> (-7.6853, 35.6034)
  line L2 (-7.7179, 35.5629) -> (-7.7179, 18.2385)
  line L3 (9.939, -35.8827) -> (-9.8049, -35.8827)
  line L4 (9.939, 89.4755) -> (9.939, -35.8827)
  line L5 (-9.8049, 89.4755) -> (9.939, 89.4755)
  line L6 (-9.8049, -35.8827) -> (-9.8049, 89.4755)
  line L7 (-6.6853, 35.6034) -> (-6.6853, 18.2148)
  line L8 (6.6748, 36.6034) -> (-5.6853, 36.6034)
  line L9 (7.6748, 18.2148) -> (7.6748, 35.6034)
  line L10 (-5.6853, 17.2148) -> (6.6748, 17.2148)
  line L11 (9, 51.0879) -> (-9.8049, 51.0879)
  line L12 (9, 52) -> (9, 51.0879)
  line L13 (-9.8049, 52) -> (9, 52)
  line L14 (-9.8049, 51.0879) -> (-9.8049, 52)
  circle C1 centre (-0.3042, -23.4586) radius 2.5
  arc A1 centre (-5.6853, 35.6034) radius 2 clockwise from (-7.6853, 35.6034) to (-7.2587, 36.8381)
  arc A2 centre (-5.6853, 18.2148) radius 2 clockwise from (-6.8798, 16.6106) to (-7.6853, 18.2148)
  arc A3 centre (-5.7179, 18.2385) radius 2 clockwise from (-6.8798, 16.6106) to (-7.7179, 18.2385)
  arc A4 centre (-5.7179, 35.5629) radius 2 clockwise from (-7.7179, 35.5629) to (-7.2587, 36.8381)
  circle C2 centre (0, 10) radius 2.75
  circle C3 centre (0, 45) radius 2.75
  arc A5 centre (-5.6853, 18.2148) radius 1 clockwise from (-5.6853, 17.2148) to (-6.6853, 18.2148)
  arc A6 centre (-5.6853, 35.6034) radius 1 clockwise from (-6.6853, 35.6034) to (-5.6853, 36.6034)
  arc A7 centre (6.6748, 35.6034) radius 1 clockwise from (6.6748, 36.6034) to (7.6748, 35.6034)
  arc A8 centre (6.6748, 18.2148) radius 1 clockwise from (7.6748, 18.2148) to (6.6748, 17.2148)
  point P29 (-9.8049, 51.0879)
  horizontal L11
  vertical L12
  horizontal L13
  vertical L14
  coincident L6 P29
extrude "Extruir41" add sketch "Boceto54" profile of L6 L11 L12 L13 L14 along normal blind 5
move "Desplazar81"
sketch "Boceto55" plane through (0, 37.8511, 0) normal (0, 1, 0) x axis (-1, 0, 0)
  line L1 (-48.1144, 82.3783) -> (-48.1144, 87.0904)
  line L2 (-15.1144, 82.3783) -> (-48.1144, 82.3783)
  line L3 (-15.1144, 87.0904) -> (-15.1144, 82.3783)
  line L4 (-48.1144, 87.0904) -> (-15.1144, 87.0904)
  line L5 (-20, 84) -> (-17, 84)
  line L6 (-20, 85) -> (-20, 84)
  line L7 (-17, 85) -> (-20, 85)
  line L8 (-17, 84) -> (-17, 85)
  horizontal L5
  vertical L6
  horizontal L7
  vertical L8
extrude "Extruir42" cut sketch "Boceto55" profile of L5 L6 L7 L8 along normal blind 0 and against normal blind 14
sketch "Boceto56" plane through (0, 0, 0) normal (1, 0, 0) x axis (0, 0, -1)
  line L1 (-68.1721, -12) -> (-65.4717, -12)
  line L2 (-68.1721, -13.9837) -> (-68.1721, -12)
  line L3 (-65.4717, -13.9837) -> (-68.1721, -13.9837)
  line L4 (-65.4717, -12) -> (-65.4717, -13.9837)
  line L5 (-65.5, -10.5) -> (-63.5438, -10.5)
  line L6 (-65.5, -13.9835) -> (-65.5, -10.5)
  line L7 (-63.5438, -13.9835) -> (-65.5, -13.9835)
  line L8 (-63.5438, -10.5) -> (-63.5438, -13.9835)
  line L9 (-69.9562, -10.5) -> (-68, -10.5)
  line L10 (-69.9562, -13.9837) -> (-69.9562, -10.5)
  line L11 (-68, -13.9837) -> (-69.9562, -13.9837)
  line L12 (-68, -10.5) -> (-68, -13.9837)
  point P12 (-69.9562, -13.9837)
  horizontal L1
  vertical L2
  horizontal L3
  vertical L4
  horizontal L5
  vertical L6
  horizontal L7
  vertical L8
  horizontal L9
  vertical L10
  horizontal L11
  vertical L12
  coincident L3 P12
extrude "Extruir43" new body sketch "Boceto56" along normal blind 2.5 bodies "Agarrar la masa"
fillet "Empalme7" radius 0.75 (= "d72")
fillet "Empalme8" radius 0.75 (= "d72")
combine "Combinar5"
move "Desplazar83"
copy_paste_bodies "CopiarPegarCuerpos2"
move "Desplazar84"
move "Desplazar85"
move "Desplazar86"
extrude "Extruir44" add of existing geometry blind 1 bodies "Agarrar la masa"
copy_paste_bodies "CopiarPegarCuerpos3"
move "Desplazar87"
extrude "Extruir45" add of existing geometry blind 1
extrude "Extruir46" add of existing geometry blind 1 bodies "Agarrar la masa  (1)"
extrude "Extruir47" add of existing geometry blind 1
move "Desplazar88"
copy_paste_bodies "CopiarPegarCuerpos4"
move "Desplazar89"
move "Desplazar90"
move "Desplazar91"
move "Desplazar92"
extrude "Extruir48" add of existing geometry blind 1 bodies "Agarrar la masa  (1) (1) (1)"
extrude "Extruir49" add of existing geometry blind 0.9
move "Desplazar93"
extrude "Extruir50" add of existing geometry blind 1 bodies "Agarrar la masa  (1) (1)"
extrude "Extruir51" add of existing geometry blind 0.9
extrude "Extruir52" add of existing geometry blind 4.9
sketch "Boceto59" plane through (0, 0, 16.2148) normal (0, 0, -1) x axis (-1, 0, 0)
  line L1 (-5.6853, 20) -> (6.6748, 20)
  line L2 (-5.6853, 9) -> (-5.6853, 20)
  line L3 (6.6748, 9) -> (-5.6853, 9)
  line L4 (6.6748, 20) -> (6.6748, 9)
  line L5 (-0.027, 18.7595) -> (-8, 18.7595)
  line L6 (-0.027, 6) -> (-0.027, 18.7595)
  line L7 (-8, 6) -> (-0.027, 6)
  line L8 (-8, 18.7595) -> (-8, 6)
  horizontal L5
  vertical L6
  horizontal L7
  vertical L8
extrude "Extruir53" cut sketch "Boceto59" profile of L2 L3 L5 L6 L7 L8 along normal blind 3 and against normal blind 27
extrude "Extruir54" add of existing geometry blind 3.5
extrude "Extruir55" add of existing geometry blind 2
extrude "Extruir56" add of existing geometry blind 2
fillet "Empalme9" radius 0.75 (= "d72")
extrude "Extruir57" add of existing geometry blind 3
move "Desplazar94"
extrude "Extruir58" add of existing geometry blind 2
extrude "Extruir59" add of existing geometry blind 2
move "Desplazar95"
extrude "Extruir60" add of existing geometry blind 2
fillet "Empalme11" radius 0.75 (= "d72")
move "Desplazar96"
fillet "Empalme12" radius 0.75 (= "d72")
fillet "Empalme13" radius 0.75 (= "d72")
fillet "Empalme14" radius 0.75 (= "d72")
move "Desplazar97"
move "Desplazar98"
move "Desplazar99"
offset_faces "CarasDesfase1" distance 1.2
offset_faces "CarasDesfase2" distance 1.2
offset_faces "CarasDesfase3" distance 0.9
offset_faces "CarasDesfase4" distance 0.9
work_plane "PlanoDeObra" RotateAngle -45 ExtraOffset 0
sketch "Boceto66" plane through (0, 1.8594, 1.8594) normal (0, 0.7071, 0.7071) x axis (1, 0, 0)
  line L1 (43, 50) -> (42, 50)
  line L2 (43, 45.5) -> (43, 50)
  line L3 (42, 45.5) -> (43, 45.5)
  line L4 (42, 50) -> (42, 45.5)
  line L5 (38.5, 50) -> (37.5, 50)
  line L6 (38.5, 45.5) -> (38.5, 50)
  line L7 (37.5, 45.5) -> (38.5, 45.5)
  line L8 (37.5, 50) -> (37.5, 45.5)
  line L9 (36.5, 50) -> (35.5, 50)
  line L10 (36.5, 45.5) -> (36.5, 50)
  line L11 (35.5, 45.5) -> (36.5, 45.5)
  line L12 (35.5, 50) -> (35.5, 45.5)
  line L13 (45, 50) -> (44, 50)
  line L14 (45, 45.5) -> (45, 50)
  line L15 (44, 45.5) -> (45, 45.5)
  line L16 (44, 50) -> (44, 45.5)
  line L17 (40.5, 50) -> (39.5, 50)
  line L18 (40.5, 45.5) -> (40.5, 50)
  line L19 (39.5, 45.5) -> (40.5, 45.5)
  line L20 (39.5, 50) -> (39.5, 45.5)
  horizontal L1
  vertical L2
  horizontal L3
  vertical L4
  horizontal L5
  vertical L6
  horizontal L7
  vertical L8
  horizontal L9
  vertical L10
  horizontal L11
  vertical L12
  horizontal L13
  vertical L14
  horizontal L15
  vertical L16
  horizontal L17
  vertical L18
  horizontal L19
  vertical L20
extrude "Extruir72" cut sketch "Boceto66" along normal blind 0 and against normal blind 20
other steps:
base_feature "Elemento base1" bodies "Brazo derecho"
step "Saliente de Fijación4" Thickness(T2) 1.5 (= "d70") named "d219" Draft Angle(DA2) 2 (= "d71") named "d220" Nominal Radius(NR2) 0.75 (= "d72") Thread Diameter(TD) 5 Head Diameter(HD) 10 Head Angle(HA) 0 Offset Position(O) 0 Offset Clearance(O2) 0 Boss Diameter(D2) 10 (= "d182 * 2") Boss Draft Angle(alpha42) 2 (= "d220") Base Fillet Radius(R2) 0.375 (= "d219 * 0.25") Outer Boss Fillet Radius(R52) 0 Step Diameter(C2) 3 Step Depth(F2) 1 Step Draft Angle(alpha32) 0 Outer Step Fillet Radius(R62) 0 Inner Step Fillet Radius(R72) 0 Inner Hole Diameter(B2) 5 Hole Draft Angle(alpha22) 0 Outer Hole Fillet Radius(R12) 0 Inner Hole Fillet Radius(R42) 0 Counterbore Diameter(A2) 5 Counterbore Depth(I2) 4 Counterbore Draft Angle(alpha12) 2 (= "d220") Outer Counterbore Fillet Radius(R32) 0 Inner Counterbore Fillet Radius(R22) 0 Countersink Angle(alpha2) 90 Inner Hole Depth(G2) 4.1 Rib Length(K2) 0 Rib Offset(L2) 0 Rib Thickness(RT2) 0 Rib Draft Angle(RD2) 0 Rib Fillet Radius(RR2) 0 Rib Outer Draft(beta12) 0 Rib Chamfer Angle(beta22) 0 Rib Outer Fillet Radius(RTR2) 0 Rib Base Fillet Radius(RBR2) 0 Rib Rotation Angle(RRO2) 0 Rib Total Angle(RAS2) 360
step "Saliente de Fijación6" Thickness(T2) 1.5 (= "d70") named "d299" Draft Angle(DA2) 2 (= "d71") named "d300" Nominal Radius(NR2) 0.75 (= "d72") Thread Diameter(TD) 5 Head Diameter(HD) 10 Head Angle(HA) 0 Offset Position(O) 0 Offset Clearance(O2) 0 Boss Diameter(D2) 10 (= "d262 * 2") Boss Draft Angle(alpha42) 2 (= "d300") Base Fillet Radius(R2) 0.375 (= "d299 * 0.25") Outer Boss Fillet Radius(R52) 0 Step Diameter(C2) 3 Step Depth(F2) 1 Step Draft Angle(alpha32) 0 Outer Step Fillet Radius(R62) 0 Inner Step Fillet Radius(R72) 0 Inner Hole Diameter(B2) 5 named "d316" Hole Draft Angle(alpha22) 0 Outer Hole Fillet Radius(R12) 0 Inner Hole Fillet Radius(R42) 0 Counterbore Diameter(A2) 5.5 (= "d262 + 0.5 mm") Counterbore Depth(I2) 2.5 (= "d316 * 0.5") Counterbore Draft Angle(alpha12) 2 (= "d300") Outer Counterbore Fillet Radius(R32) 0 Inner Counterbore Fillet Radius(R22) 0 Countersink Angle(alpha2) 90 Inner Hole Depth(G2) 4.1 Rib Length(K2) 0 Rib Offset(L2) 0 Rib Thickness(RT2) 0 Rib Draft Angle(RD2) 0 Rib Fillet Radius(RR2) 0 Rib Outer Draft(beta12) 0 Rib Chamfer Angle(beta22) 0 Rib Outer Fillet Radius(RTR2) 0 Rib Base Fillet Radius(RBR2) 0 Rib Rotation Angle(RRO2) 0 Rib Total Angle(RAS2) 360
base_feature "Elemento base2" bodies "Agarrar la masa", "Agarrar la masa  (1)"
base_feature "Elemento base3" bodies "Agarrar la masa  (1)", "Agarrar la masa  (1) (1)"
base_feature "Elemento base4" bodies "Agarrar la masa  (1) (1)", "Agarrar la masa  (1) (1) (1)"
step "Conexión por perno2"
component_insert "Inserción de componente8"
step "Conexión por perno3"
component_insert "Inserción de componente9"
step "Labio5" Height (A) 0.5 (= "d70 / 3") Width (B) 0.5 (= "d70 / 3") Shoulder Width (C) 0 Inside Angle (a1) 2 (= "d71") Outside Angle (a2) 2 (= "d71") Reveal Height (D) 0.5 (= "d73") Clearance (E) 0.1 (= "d74")
as_built_joint "Conforme a obra21"
as_built_joint "Conforme a obra22"
named bodies: "Tapa modelo principal", "Cuerpo modelo principal", "Cuerpo sensor movimiento", "Tapa protector sensor", "motor vibrador", "Tapa cabidad motor", "Brazo derecho", "Cabidad motor", "Modelo principal", "Sostenedor de ESP32", "Sostenedor de brazo", "Agarrar la masa", "Agarrar la masa  (1)", "Agarrar la masa  (1) (1)", "Agarrar la masa  (1) (1) (1)"

design "ESP32S3 Super Mini"
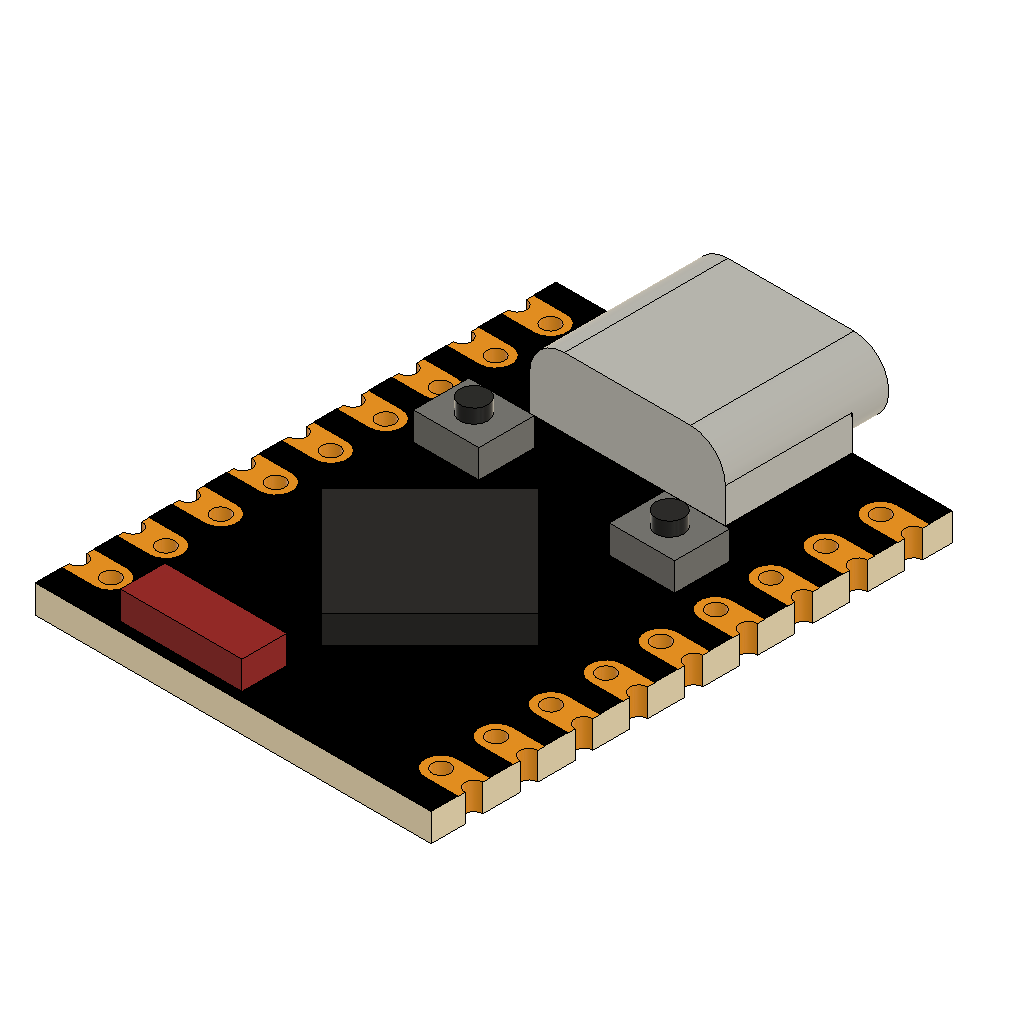
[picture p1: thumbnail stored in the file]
description: HOOPS Exchange Step
part number: root
base_feature "Base Feature"

design "TOF"
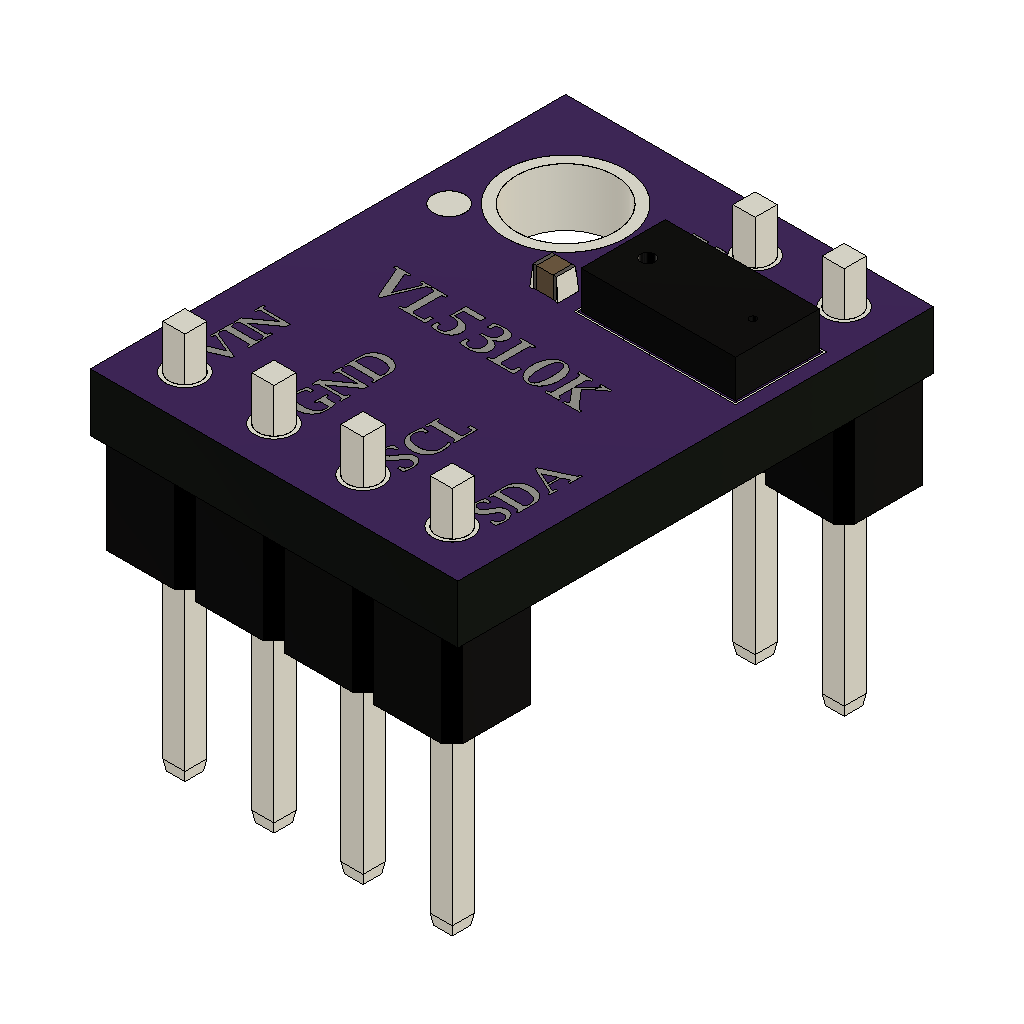
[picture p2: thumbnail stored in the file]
description: Part Number
part number: TOF
part number: 4X1
part number: 2x1 male header pins
base_feature "Base Feature1"
base_feature "Base Feature1"
base_feature "Base Feature1"
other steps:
create_component "CreateComponent1"
create_component "CreateComponent2"

design "Tornillo grueso en forma de rosca sin ranura de arandela hexagonal 30° 5x8 Acero al carbono Negro"
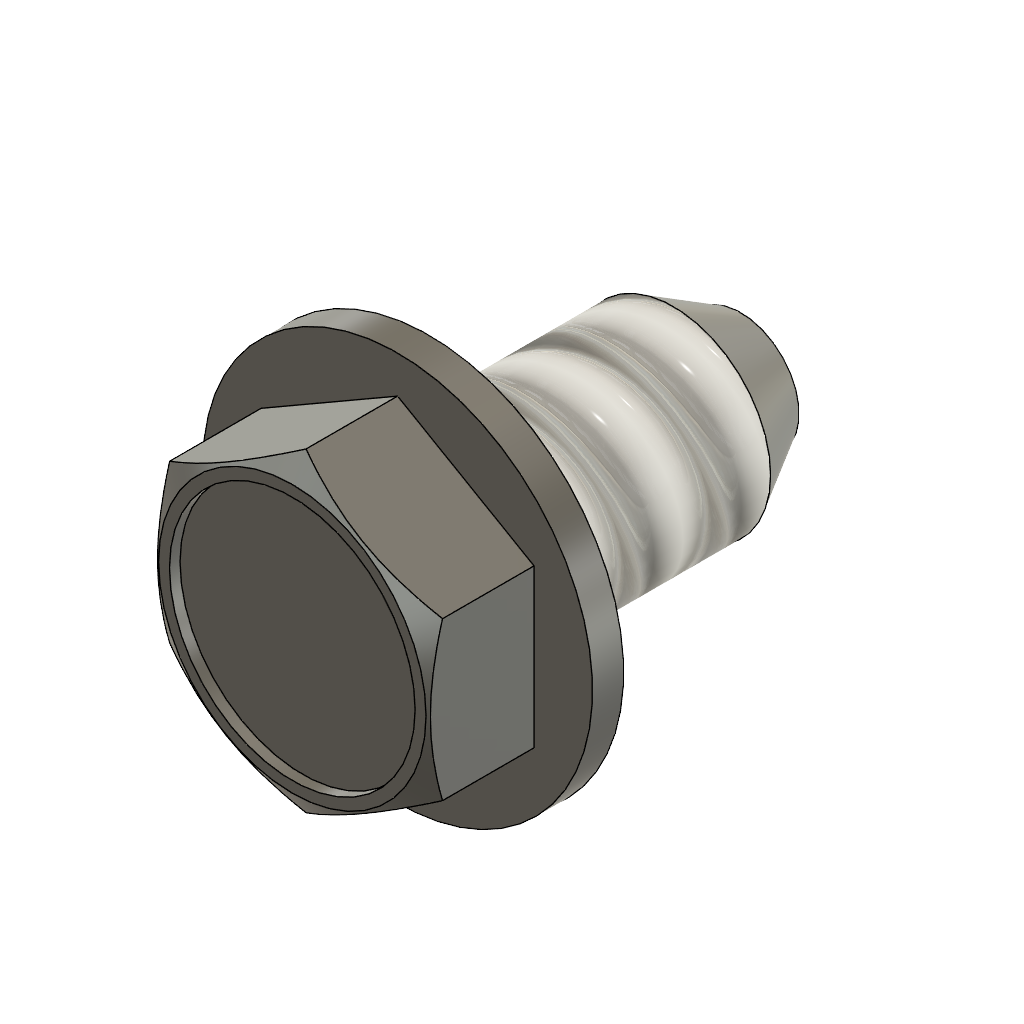
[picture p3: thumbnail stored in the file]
description: arrangementsContainer
parameter "NLG" = 8
parameter "KOH" = 3.5
parameter "KOD" = 10
parameter "NND" = 5
parameter "KOF" = 0.8
parameter "SW" = 7
sketch "Sketch1" plane through (0, 0, 0) normal (0, 1, 0) x axis (1, 0, 0)
  line L1 (-2.5, 8) -> (-2.5, 0)
  line L2 (0, 8) -> (-2.5, 8)
  line L3 (0, -3.5) -> (0, 8)
  line L4 (-5, 0) -> (-2.5, 0)
  line L5 (-5, -3.5) -> (-5, 0)
  line L6 (0, -3.5) -> (-5, -3.5)
  point P1 (0, 0)
  point P2 (0, -3.5)
  point P5 (0, 8)
  point P8 (0, -3.5)
  point P6 (-5, 0)
  point P7 (-5, -3.5)
  perpendicular L1 L2
  collinear P1 P2 P5
  perpendicular L1 L4
  coincident P1 L4
  vertical L1
  vertical L3
  perpendicular L4 L5
  perpendicular L5 L6
  coincident P2 L6
  coincident P2 P8
  dimension "d9" = 5 (= "NND")
  dimension "d66" = 10 (= "KOD")
  dimension "d68" distance P1 P5 = 8 (= "NLG")
  dimension "d73" distance P6 P7 = 3.5 (= "KOH")
revolve "Revolve1" sketch "Sketch1" AlongAngle 360
work_plane "WorkPlane2" AlongDistance 3.5 (= "KOH")
sketch "Sketch6" plane through (0, 0, 3.5) normal (0, 0, 1) x axis (1, 0, 0)
  line L1 (-3.5, 0) -> (0, 0)
  line L2 (-3.5, -2.0207) -> (0, 0)
  line L3 (2.5495, 0) -> (0, 0)
  line L4 (-3.5, -2.0207) -> (-3.5, 2.0207)
  line L5 (-3.5, 2.0207) -> (0, 0)
  line L6 (0, 4.0415) -> (0, 0)
  line L7 (0, 4.0415) -> (-3.5, 2.0207)
  line L8 (0, 4.0415) -> (3.5, 2.0207)
  line L9 (3.5, 2.0207) -> (0, 0)
  line L10 (-3.5, -2.0207) -> (0, -4.0415)
  line L11 (3.5, -2.0207) -> (0, -4.0415)
  line L12 (3.5, -2.0207) -> (3.5, 2.0207)
  circle C1 centre (0, 0) radius 5
  point P2 (0, 0)
  point P3 (0, 0)
  point P5 (0, 0)
  point P4 (-3.5, 0)
  point P9 (-3.5, -2.0207)
  point P6 (-3.5, -2.0207)
  point P10 (0, 0)
  point P11 (-3.5, 2.0207)
  point P12 (0, 0)
  point P13 (0, 4.0415)
  point P8 (-3.5, 2.0207)
  point P14 (-3.5, 2.0207)
  point P15 (0, 4.0415)
  point P18 (0, 0)
  point P19 (3.5, 2.0207)
  point P16 (3.5, 2.0207)
  point P17 (0, 4.0415)
  point P20 (0, -4.0415)
  point P21 (-3.5, -2.0207)
  point P22 (0, -4.0415)
  point P23 (3.5, -2.0207)
  point P24 (3.5, 2.0207)
  point P25 (3.5, -2.0207)
  coincident P2 P3
  horizontal L1
  horizontal L3
  coincident P2 P5
  perpendicular L1 L4
  midpoint P4 L4
  coincident L2 P9
  coincident P6 L4
  symmetric L1 P5 P10
  symmetric L1 P6 P11
  symmetric P5 L5 P12
  symmetric P6 L5 P13
  symmetric P8 L5 P14
  symmetric P9 L5 P15
  symmetric P10 L6 P18
  symmetric P11 L6 P19
  symmetric L6 P14 P16
  symmetric L6 P15 P17
  symmetric P8 L9 P20
  symmetric P9 L9 P21
  symmetric P14 L9 P22
  symmetric P15 L9 P23
  symmetric P16 L9 P24
  symmetric P17 L9 P25
  dimension "d76" distance P3 P4 = 3.5 (= "SW / 2")
  dimension "d77" angle L2 L3 = 150
extrude "Extrude2" cut sketch "Sketch6" profile of C1 L4 L7 L8 L10 L11 L12 no distance stored
sketch "Sketch8" plane through (0, 0, 3.5) normal (0, 0, 1) x axis (1, 0, 0)
  circle C1 centre (0, 0) radius 3.43
  circle C2 centre (0, 0) radius 6
  point P1 (0, 0)
  point P2 (0, 0)
  point P3 (0, 0)
  coincident P1 P2
  coincident P1 P3
  dimension "d80" diameter C1 = 6.86 (= "SW * 0.98")
  dimension "d81" diameter C2 = 12 (= "KOD * 1.2")
extrude "Extrude3" cut sketch "Sketch8" no distance stored taper -60
sketch "Sketch9" plane through (0, 0, 3.5) normal (0, 0, 1) x axis (1, 0, 0)
  circle C1 centre (0, 0) radius 3.15
  point P1 (0, 0)
  point P2 (0, 0)
  coincident P1 P2
  dimension "d84" diameter C1 = 6.3 (= "SW * 0.9")
extrude "Extrude4" cut sketch "Sketch9" against normal blind 0.27 (magnitude of "( -KOH + KOF ) * 0.1")
work_plane "WorkPlane1" AlongDistance 3.95 (= "KOH + KOF - KOH * 0.1")
sketch "Sketch5" plane through (0, 0, 0) normal (0, 1, 0) x axis (1, 0, 0)
  line L1 (0, 8) -> (-2.5, 8)
  line L2 (-2.5, 8) -> (-2.5, 0)
  line L3 (-1.5, 8) -> (-2.5, 6.2679)
  point P6 (-2.5, 6.2679)
  point P7 (-1.5, 8)
  point P2 (-2.5, 8)
  coincident L2 P6
  coincident L1 P7
  dimension "d39" angle L2 L3 = 30
  dimension "d40" distance P2 P7 = 1 (= "NND * 0.2")
thread "Thread1" ThreadOffset 0 ThreadLength 10
revolve "Revolve2" sketch "Sketch5" AlongAngle 360
joint_origin "JointOrigin1" OffsetX 0 OffsetY 0 OffsetZ 0 AngleZ 0

design "przelacznik"
part number: przelacznik
base_feature "Base Feature"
